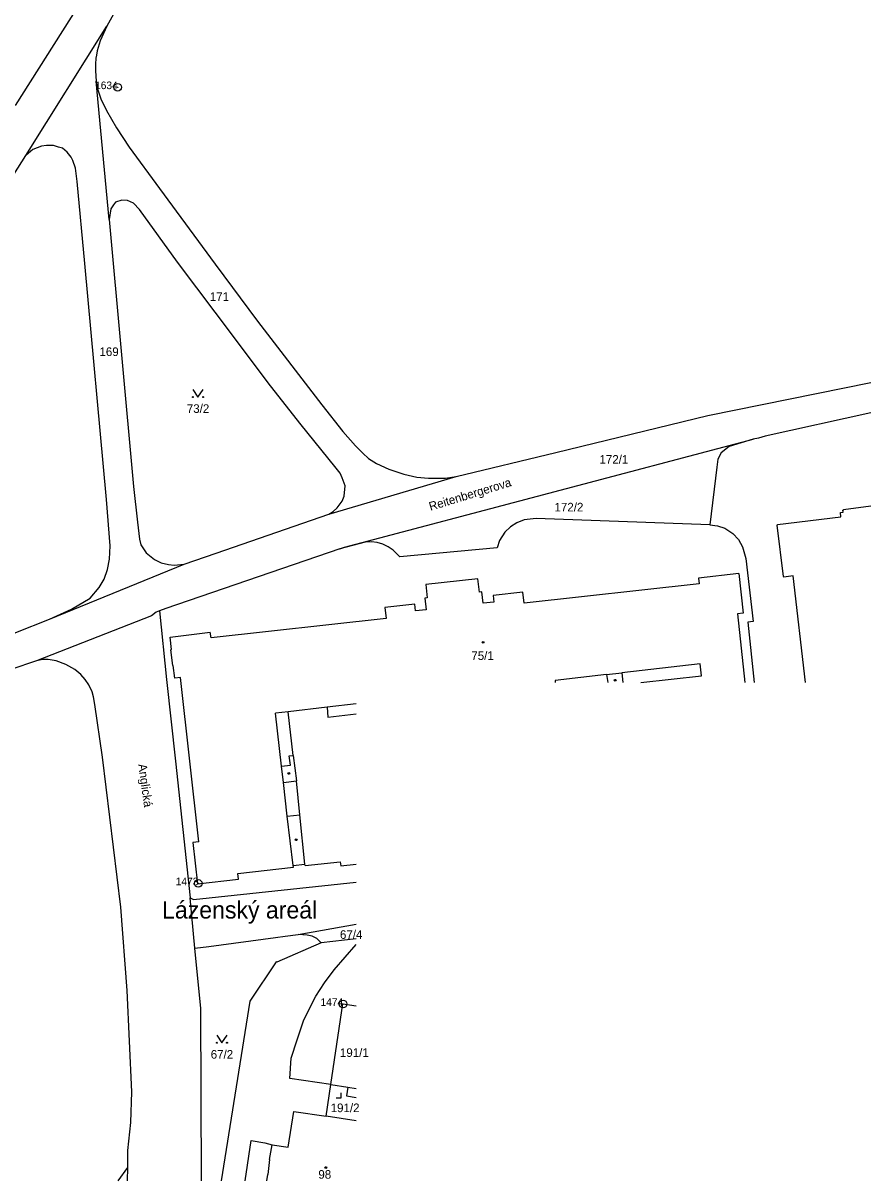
# Model space of a CAD drawing. Extents: x -866441 to -866144, y -1037389 to -1036968.
# Drawn here: x -866310.8 to -866143.8, y -1037388.9 to -1037160.7 of the extents above; entities that cross this region are included whole.
import ezdxf

# ---------------------------------------------------------------- set-up
doc = ezdxf.new("R2010")
doc.units = 0
for name, color, linetype in [('Hranice parcel', 7, 'Continuous'), ('Parcelní čísla', 7, 'Continuous'), ('Pop  PČ popisy', 7, 'Continuous'), ('Vnitřní kresba', 7, 'Continuous'), ('Značky bodu BP', 7, 'Continuous'), ('Značky budov', 7, 'Continuous'), ('Značky kultur', 7, 'Continuous')]:
    doc.layers.add(name, color=color, linetype=linetype)

msp = doc.modelspace()

# ---------------------------------------------------------------- linework, layer by layer
at = {"layer": 'Hranice parcel'}
for p, q in [((-866300.13, -1037157.61), (-866312.39, -1037176.98)), ((-866310.32, -1037186.83), (-866294.34, -1037161.34)), ((-866296.59, -1037170.16), (-866296.44, -1037172.17)), ((-866293.89, -1037199.42), (-866296.44, -1037172.17)), ((-866250.63, -1037257.52), (-866225.49, -1037250.1)), ((-866243.45, -1037263), (-866248.46, -1037264.33)), ((-866305.66, -1037278.15), (-866279.11, -1037267.31)), ((-866276.98, -1037343.04), (-866277.96, -1037333.11)), ((-866256.68, -1037340.3), (-866245.22, -1037338.29)), ((-866245.22, -1037341.17), (-866252.11, -1037341.96)), ((-866251.12, -1037376.13), (-866250.19, -1037369.89)), ((-866290.27, -1037388.86), (-866290.24, -1037386.26))]:
    msp.add_line(p, q, dxfattribs=at)
for points in [[(-866202.32, -1037019.11), (-866205.51, -1037023.16), (-866214.08, -1037035.18), (-866217.27, -1037039.83), (-866223.47, -1037049.2), (-866275.07, -1037129.84), (-866289.8, -1037153.5), (-866292.71, -1037158.35), (-866294.34, -1037161.34)], [(-866294.34, -1037161.34), (-866295.66, -1037164.23), (-866296.29, -1037166.18)], [(-866296.29, -1037166.18), (-866296.49, -1037167.45), (-866296.51, -1037167.59), (-866296.6, -1037168.87), (-866296.59, -1037170.16)], [(-866296.44, -1037172.17), (-866296.19, -1037173.69), (-866295.52, -1037175.68), (-866294.4, -1037177.98), (-866292.42, -1037181.37), (-866289.93, -1037185.15), (-866284, -1037193.29), (-866273.01, -1037208.23), (-866264.63, -1037219.46), (-866251.99, -1037235.97), (-866247.82, -1037241.19), (-866245.35, -1037244.05), (-866243.91, -1037245.47), (-866242.78, -1037246.49), (-866241.18, -1037247.51), (-866238.81, -1037248.65), (-866235.8, -1037249.64), (-866233.26, -1037250.17), (-866230.96, -1037250.39), (-866227.59, -1037250.38), (-866225.49, -1037250.1)], [(-866305.66, -1037278.15), (-866301.35, -1037276.21), (-866297.67, -1037274.01), (-866295.85, -1037271.95), (-866294.88, -1037270.27), (-866294.2, -1037268.37), (-866293.8, -1037266.37), (-866293.69, -1037263.71), (-866294.4, -1037254.62), (-866298.67, -1037208.12), (-866300.2, -1037191.91), (-866300.54, -1037189.31), (-866301.03, -1037187.78), (-866301.38, -1037187.17), (-866302.16, -1037186.13), (-866303.1, -1037185.36), (-866303.91, -1037185.15), (-866304.87, -1037184.85), (-866306.27, -1037184.84), (-866307.26, -1037184.99), (-866308.95, -1037185.64), (-866310.32, -1037186.83)], [(-866375.03, -1037299.56), (-866374.62, -1037298.06), (-866373.96, -1037296.2), (-866373.2, -1037294.32), (-866372.2, -1037291.8), (-866371.29, -1037289.89), (-866369.19, -1037285.61), (-866363.39, -1037275.2), (-866358.83, -1037267.24), (-866350.73, -1037253.34), (-866344.87, -1037243.59), (-866336.21, -1037228.98), (-866322.61, -1037206.41), (-866317.13, -1037197.53), (-866310.32, -1037186.83)], [(-866250.63, -1037257.52), (-866249.72, -1037256.96), (-866248.95, -1037256.27), (-866247.98, -1037254.9), (-866247.61, -1037253.94), (-866247.4, -1037251.94), (-866247.95, -1037250.32), (-866248.4, -1037249.44), (-866249.15, -1037248.44), (-866256.35, -1037239.57), (-866262.53, -1037231.61), (-866269.22, -1037222.76), (-866280.41, -1037207.81), (-866287.93, -1037197.48), (-866289.08, -1037196.23), (-866290.25, -1037195.71), (-866291.39, -1037195.64), (-866292.64, -1037196.03), (-866293.01, -1037196.52), (-866293.59, -1037197.34), (-866293.89, -1037199.42)], [(-866293.89, -1037199.42), (-866289.11, -1037252.01), (-866288.28, -1037259.07), (-866287.92, -1037262.39), (-866287.64, -1037263.55), (-866286.61, -1037265.11), (-866284.96, -1037266.4), (-866283.62, -1037267.1), (-866282.19, -1037267.44), (-866281.09, -1037267.54), (-866279.11, -1037267.31)], [(-866225.49, -1037250.1), (-866205.84, -1037245.34), (-866175.91, -1037238.08), (-866143.78, -1037231.55)], [(-866143.78, -1037237.52), (-866164.63, -1037242.15), (-866165.95, -1037242.52), (-866166.95, -1037242.73)], [(-866248.46, -1037264.33), (-866247.53, -1037264), (-866166.95, -1037242.73)], [(-866166.95, -1037242.73), (-866171.7, -1037244.17), (-866173.28, -1037245.43), (-866173.93, -1037246.65), (-866174.11, -1037248.23), (-866175.53, -1037259.6)], [(-866279.11, -1037267.31), (-866272.8, -1037265.2), (-866250.63, -1037257.52)], [(-866175.53, -1037259.6), (-866209.77, -1037258.35), (-866212.1, -1037258.6), (-866213.55, -1037259.18), (-866214.81, -1037260.01), (-866215.92, -1037261.04), (-866216.96, -1037262.67), (-866217.45, -1037264.14), (-866236.62, -1037265.93)], [(-866175.53, -1037259.6), (-866174.02, -1037259.76), (-866172.54, -1037260.26), (-866170.99, -1037261.27), (-866169.88, -1037262.46), (-866169.05, -1037263.96), (-866168.39, -1037266.23), (-866167, -1037278.65)], [(-866248.46, -1037264.33), (-866282.75, -1037276.06), (-866283.98, -1037276.57)], [(-866236.62, -1037265.93), (-866237.94, -1037264.57), (-866238.92, -1037263.91), (-866239.98, -1037263.41), (-866241.11, -1037263.09), (-866242.21, -1037262.95), (-866243.45, -1037263)], [(-866375.03, -1037299.56), (-866375.13, -1037301.01), (-866375.04, -1037301.56), (-866374.74, -1037302.65), (-866374.28, -1037303.65), (-866373.72, -1037304.45), (-866373.12, -1037305.04), (-866372.13, -1037305.69), (-866371.2, -1037306), (-866370.07, -1037306.19), (-866368.92, -1037306.17), (-866367.46, -1037305.76), (-866365.86, -1037305.16), (-866363.36, -1037304.06), (-866329.22, -1037287.85), (-866312.3, -1037280.78), (-866305.66, -1037278.15)], [(-866283.98, -1037276.57), (-866284.61, -1037276.83), (-866285.56, -1037277.51), (-866308.19, -1037286.36)], [(-866283.98, -1037276.57), (-866282.57, -1037290.06), (-866280.83, -1037306.19), (-866277.96, -1037333.11)], [(-866167, -1037278.65), (-866168.03, -1037278.76), (-866166.81, -1037290.69)], [(-866308.19, -1037286.36), (-866313.27, -1037288.13), (-866327.97, -1037294.37), (-866334.34, -1037297.29), (-866342.02, -1037300.83), (-866354.66, -1037306.93), (-866359.28, -1037309.3), (-866362.25, -1037310.96), (-866365.45, -1037312.87), (-866366.46, -1037313.55), (-866367.93, -1037314.63), (-866369.92, -1037316.18), (-866371.5, -1037317.58), (-866374.41, -1037320.72), (-866375.94, -1037322.82), (-866377.5, -1037325.43), (-866378.49, -1037327.19), (-866379.7, -1037329.61), (-866380.55, -1037331.74)], [(-866290.24, -1037386.26), (-866290.19, -1037382.87), (-866289.6, -1037377.37), (-866289.46, -1037371.3), (-866290.33, -1037351.36), (-866291.58, -1037334.93), (-866295.22, -1037305.39), (-866296.69, -1037295), (-866296.99, -1037293.48), (-866297.27, -1037292.5), (-866297.91, -1037291.14), (-866298.65, -1037290.04), (-866299.51, -1037289.06), (-866300.65, -1037288.08), (-866302.42, -1037287.09), (-866304.37, -1037286.38), (-866305.94, -1037286.1), (-866306.98, -1037286.14), (-866308.19, -1037286.36)], [(-866277.96, -1037333.11), (-866277.25, -1037333.45), (-866245.22, -1037329.98)], [(-866276.98, -1037343.04), (-866274.28, -1037342.67), (-866261.12, -1037340.88), (-866259.19, -1037340.62), (-866256.68, -1037340.3)], [(-866252.11, -1037341.96), (-866252.97, -1037341.13), (-866253.9, -1037340.65), (-866254.87, -1037340.42), (-866256.68, -1037340.3)], [(-866252.11, -1037341.96), (-866260.83, -1037345.77), (-866260.97, -1037345.68), (-866266.2, -1037353.42), (-866271.84, -1037388.86)], [(-866258, -1037364.71), (-866256.87, -1037361.09), (-866255.56, -1037357.1), (-866253.19, -1037352.45), (-866251.49, -1037349.85), (-866249.57, -1037347.28), (-866245.22, -1037342.28)], [(-866275.68, -1037388.86), (-866275.81, -1037354.92), (-866276.98, -1037343.04)], [(-866250.19, -1037369.89), (-866247.82, -1037354.01), (-866245.22, -1037354.37)], [(-866250.19, -1037369.89), (-866258.28, -1037368.7), (-866258, -1037364.71)], [(-866250.19, -1037369.89), (-866246.88, -1037370.39), (-866247.14, -1037372.12), (-866245.22, -1037372.41)], [(-866267.09, -1037388.86), (-866265.88, -1037380.93), (-866263.2, -1037381.39), (-866261.79, -1037381.73), (-866258.65, -1037382.25), (-866257.51, -1037375.16), (-866251.12, -1037376.13)], [(-866245.22, -1037377.03), (-866251.12, -1037376.13)], [(-866292.13, -1037388.86), (-866290.24, -1037386.26)]]:
    msp.add_lwpolyline(points, dxfattribs=at)
at = {"layer": 'Vnitřní kresba'}
for p, q in [((-866149.19, -1037256.54), (-866143.78, -1037255.88)), ((-866162.17, -1037259.54), (-866149.67, -1037258.01)), ((-866149.77, -1037257.17), (-866149.27, -1037257.11)), ((-866149.67, -1037258.01), (-866149.77, -1037257.17)), ((-866149.32, -1037256.71), (-866149.17, -1037256.69)), ((-866149.27, -1037257.11), (-866149.32, -1037256.71)), ((-866149.17, -1037256.69), (-866149.19, -1037256.54)), ((-866162.26, -1037259.65), (-866162.16, -1037259.64)), ((-866161.02, -1037269.79), (-866162.26, -1037259.65)), ((-866162.16, -1037259.64), (-866162.17, -1037259.54)), ((-866169.81, -1037269.19), (-866177.74, -1037270.07)), ((-866169.81, -1037269.19), (-866168.94, -1037277.03)), ((-866159.1, -1037269.65), (-866160.91, -1037269.88)), ((-866156.64, -1037290.69), (-866159.1, -1037269.65)), ((-866221.23, -1037270.2), (-866231.5, -1037271.34)), ((-866231.5, -1037271.34), (-866231.21, -1037273.97)), ((-866220.94, -1037272.83), (-866221.23, -1037270.2)), ((-866177.61, -1037271.21), (-866212.1, -1037275.04)), ((-866177.74, -1037270.07), (-866177.61, -1037271.21)), ((-866160.92, -1037269.78), (-866161.02, -1037269.79)), ((-866160.91, -1037269.88), (-866160.92, -1037269.78)), ((-866231.21, -1037273.97), (-866231.7, -1037274.03)), ((-866231.7, -1037274.03), (-866231.45, -1037276.31)), ((-866220.42, -1037272.77), (-866220.94, -1037272.83)), ((-866220.17, -1037275.06), (-866220.42, -1037272.77)), ((-866212.34, -1037272.88), (-866218.23, -1037273.54)), ((-866218.23, -1037273.54), (-866218.08, -1037274.83)), ((-866212.1, -1037275.04), (-866212.34, -1037272.88)), ((-866233.68, -1037275.25), (-866239.56, -1037275.9)), ((-866239.56, -1037275.9), (-866239.33, -1037278.06)), ((-866233.54, -1037276.54), (-866233.68, -1037275.25)), ((-866231.45, -1037276.31), (-866233.54, -1037276.54)), ((-866218.08, -1037274.83), (-866220.17, -1037275.06)), ((-866239.33, -1037278.06), (-866273.79, -1037281.89)), ((-866168.94, -1037277.03), (-866170.08, -1037277.16)), ((-866170.08, -1037277.16), (-866168.6, -1037290.69)), ((-866281.87, -1037281.7), (-866273.98, -1037280.75)), ((-866273.79, -1037281.89), (-866273.98, -1037280.75)), ((-866281.59, -1037284.19), (-866281.87, -1037281.7)), ((-866281.71, -1037284.2), (-866281.59, -1037284.19)), ((-866281.37, -1037287.33), (-866281.71, -1037284.2)), ((-866281.25, -1037287.32), (-866281.37, -1037287.33)), ((-866280.97, -1037289.8), (-866281.25, -1037287.32)), ((-866177.41, -1037286.97), (-866192.89, -1037288.76)), ((-866177.13, -1037289.34), (-866177.41, -1037286.97)), ((-866279.83, -1037289.68), (-866280.97, -1037289.8)), ((-866276.24, -1037322.08), (-866279.83, -1037289.68)), ((-866195.85, -1037289.1), (-866206.03, -1037290.27)), ((-866195.85, -1037289.1), (-866192.89, -1037288.76)), ((-866195.85, -1037289.1), (-866195.65, -1037290.69)), ((-866192.89, -1037288.76), (-866192.64, -1037290.69)), ((-866189.13, -1037290.69), (-866177.13, -1037289.34)), ((-866206.03, -1037290.27), (-866205.98, -1037290.69)), ((-866258.6, -1037296.47), (-866261.14, -1037296.73)), ((-866259.94, -1037307.17), (-866261.14, -1037296.73)), ((-866250.96, -1037295.54), (-866258.6, -1037296.47)), ((-866257.6, -1037305.02), (-866258.6, -1037296.47)), ((-866245.22, -1037294.89), (-866250.96, -1037295.54)), ((-866250.96, -1037295.54), (-866250.81, -1037297.47)), ((-866250.81, -1037297.47), (-866245.22, -1037296.84)), ((-866258.4, -1037305.13), (-866257.6, -1037305.02)), ((-866258.18, -1037306.95), (-866258.4, -1037305.13)), ((-866257.6, -1037305.02), (-866257, -1037310.01)), ((-866259.94, -1037307.17), (-866258.18, -1037306.95)), ((-866259.57, -1037310.35), (-866259.94, -1037307.17)), ((-866259.57, -1037310.35), (-866257, -1037310.01)), ((-866258.8, -1037317), (-866259.57, -1037310.35)), ((-866256.35, -1037316.72), (-866257, -1037310.01)), ((-866258.8, -1037317), (-866256.35, -1037316.72)), ((-866257.63, -1037326.7), (-866258.8, -1037317)), ((-866255.33, -1037326.46), (-866256.35, -1037316.72)), ((-866276.24, -1037322.08), (-866277.38, -1037322.21)), ((-866277.38, -1037322.21), (-866276.48, -1037330.31)), ((-866257.63, -1037326.7), (-866255.33, -1037326.46)), ((-866255.3, -1037326.75), (-866255.33, -1037326.46)), ((-866255.3, -1037326.75), (-866248.34, -1037325.98)), ((-866248.34, -1037325.98), (-866248.25, -1037326.79)), ((-866248.25, -1037326.79), (-866245.22, -1037326.45)), ((-866268.51, -1037328.27), (-866257.59, -1037327.06)), ((-866268.39, -1037329.41), (-866268.51, -1037328.27)), ((-866257.59, -1037327.06), (-866257.63, -1037326.7)), ((-866276.48, -1037330.31), (-866268.39, -1037329.41)), ((-866246.88, -1037370.39), (-866245.22, -1037370.64)), ((-866262.27, -1037384.63), (-866261.79, -1037381.73)), ((-866262.27, -1037384.63), (-866262.62, -1037387.58)), ((-866262.84, -1037388.86), (-866262.62, -1037387.58))]:
    msp.add_line(p, q, dxfattribs=at)
at = {"layer": 'Značky bodu BP'}
for centre, radius in [((-866292.22, -1037173.37), 0.75), ((-866292.22, -1037173.37), 0.03), ((-866276.33, -1037330.25), 0.75), ((-866276.33, -1037330.25), 0.03), ((-866247.8, -1037354.01), 0.75), ((-866247.8, -1037354.01), 0.03)]:
    msp.add_circle(centre, radius, dxfattribs=at)
at = {"layer": 'Značky budov'}
for centre in [(-866220.21, -1037282.74), (-866194.17, -1037290.22), (-866258.48, -1037308.57), (-866257.05, -1037321.65), (-866251.19, -1037386.25)]:
    msp.add_circle(centre, 0.175, dxfattribs=at)
at = {"layer": 'Značky kultur'}
for p, q in [((-866248.18, -1037372.51), (-866248.18, -1037371.51)), ((-866249.18, -1037372.51), (-866248.18, -1037372.51))]:
    msp.add_line(p, q, dxfattribs=at)
for points in [[(-866277.39, -1037232.91), (-866276.39, -1037234.41), (-866275.39, -1037232.91)], [(-866272.67, -1037360.15), (-866271.67, -1037361.65), (-866270.67, -1037360.15)]]:
    msp.add_lwpolyline(points, dxfattribs=at)
for centre in [(-866277.39, -1037234.41), (-866275.39, -1037234.41), (-866272.67, -1037361.65), (-866270.67, -1037361.65)]:
    msp.add_circle(centre, 0.1, dxfattribs=at)

# ---------------------------------------------------------------- texts
at = {"layer": 'Parcelní čísla'}
for s, p in [('171', (-866274.06, -1037215.47)), ('169', (-866295.81, -1037226.33)), ('73/2', (-866278.59, -1037237.54)), ('172/1', (-866197.27, -1037247.55)), ('172/2', (-866206.13, -1037256.96)), ('75/1', (-866222.52, -1037286.22)), ('67/4', (-866248.41, -1037341.18)), ('67/2', (-866273.88, -1037364.78)), ('191/1', (-866248.42, -1037364.44)), ('191/2', (-866250.24, -1037375.32)), ('98', (-866252.67, -1037388.44))]:
    msp.add_text(s, height=1.7, dxfattribs=at).set_placement(p)
at = {"layer": 'Pop  PČ popisy'}
for s, rotation, p in [('Reitenbergerova', 17, (-866230.57, -1037256.84)), ('Anglická', 278, (-866288.19, -1037306.81))]:
    msp.add_text(s, height=1.7, rotation=rotation, dxfattribs=at).set_placement(p)
msp.add_text('Lázenský areál', height=3.4, dxfattribs=at).set_placement((-866283.47, -1037337.17))
at = {"layer": 'Značky bodu BP'}
for s, p in [('1634', (-866296.67, -1037173.74)), ('1473', (-866280.78, -1037330.62)), ('1474', (-866252.25, -1037354.39))]:
    msp.add_text(s, height=1.5, dxfattribs=at).set_placement(p)

doc.saveas('drawing.dxf')
